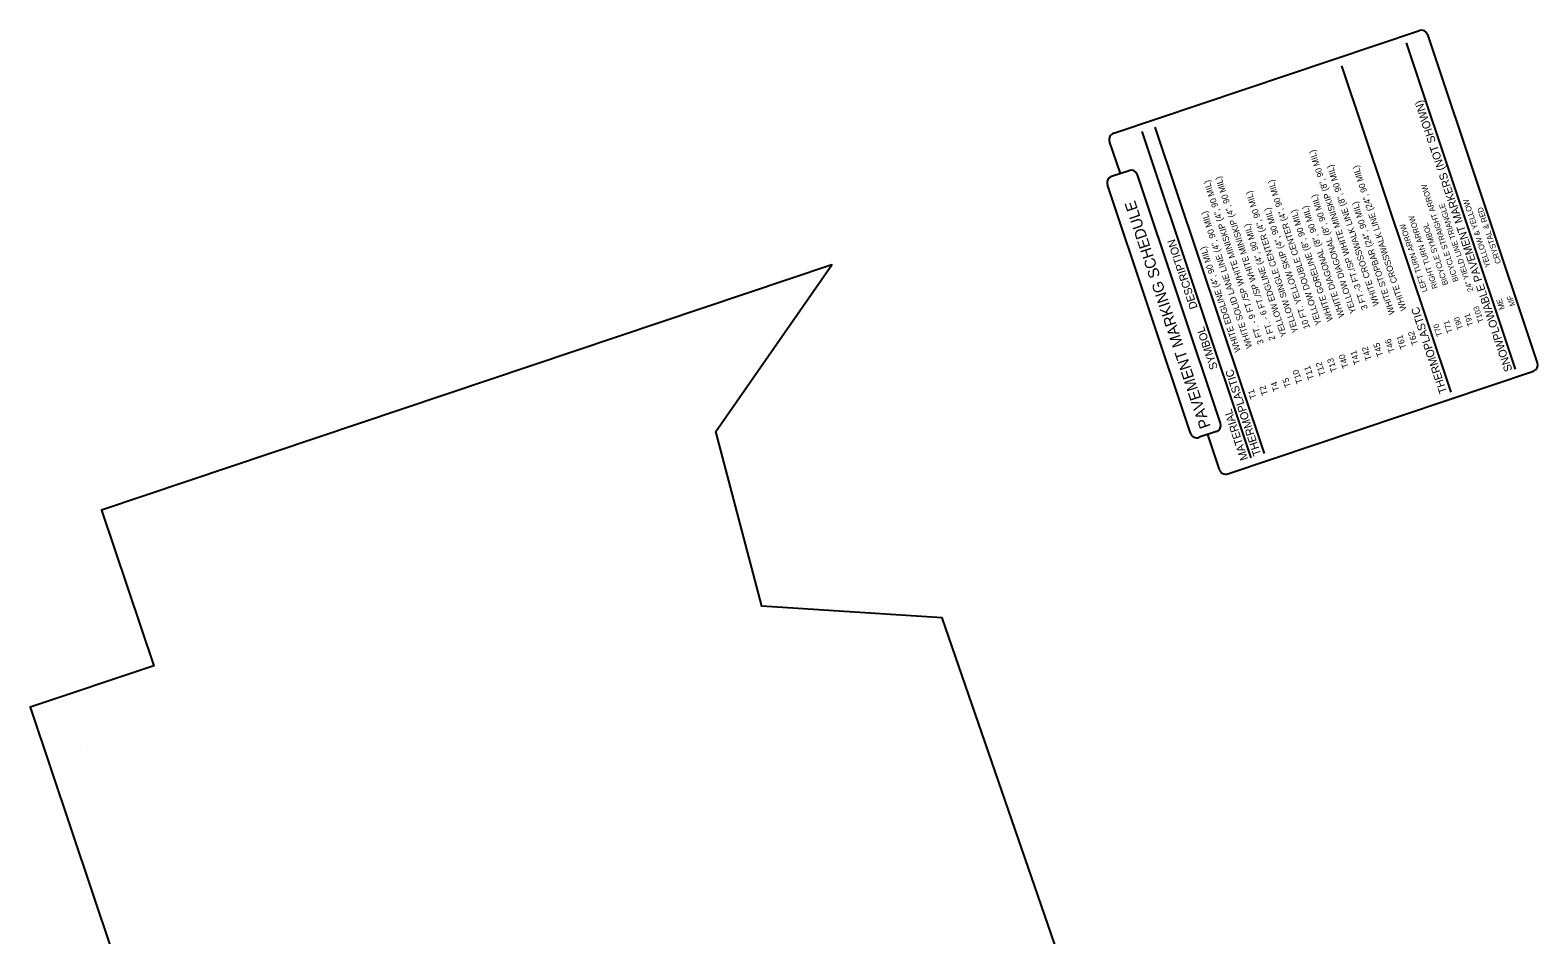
# Model space of a CAD drawing. Extents: x 1615560 to 1617263, y 903232 to 905275.
import ezdxf

# ---------------------------------------------------------------- set-up
doc = ezdxf.new("R2010")
doc.units = 0
for name, color, linetype in [('DEV BORDER CELL', 7, 'Continuous'), ('Gray Area Fill Shapes', 7, 'Continuous'), ('Sheet Layout Plan Border', 7, 'Continuous'), ('Sheet North Arrow Point CELL', 7, 'Continuous'), ('Sheet Title CELL', 7, 'Continuous')]:
    doc.layers.add(name, color=color, linetype=linetype)

msp = doc.modelspace()

# ---------------------------------------------------------------- linework, layer by layer
at = {"layer": 'DEV BORDER CELL'}
for p, q in [((1617238.1, 904891.9), (1617114.8, 905260.3)), ((1617165.3, 904866), (1617041.9, 905234.3)), ((1616939.6, 904791.9), (1616816.3, 905160.3)), ((1616954.4, 904796.8), (1616831.1, 905165.3))]:
    msp.add_line(p, q, dxfattribs=at)
at = {"layer": 'Sheet Layout Plan Border'}
msp.add_lwpolyline([(1616672.6, 903656.2), (1616919.8, 903656.8), (1616590.6, 904611.2), (1616386.8, 904624.4), (1616334.8, 904821.6), (1616466, 905009.6), (1615641.1, 904732.9), (1615700, 904557.2), (1615560.3, 904510.3), (1615954.2, 903336.2)], close=True, dxfattribs=at)
at = {"layer": 'Sheet North Arrow Point CELL'}
msp.add_line((1615617.6, 904466.6), (1615617.6, 904466.6), dxfattribs=at)
at = {"layer": 'Sheet Title CELL'}
for p, q in [((1616784.3, 905158.3), (1617129.6, 905274.3)), ((1617263, 904899.2), (1617138.9, 905269.6)), ((1616791.8, 905112.7), (1616779.6, 905149)), ((1616801.8, 905116), (1616781.8, 905109.4)), ((1616905, 904830.9), (1616811.1, 905111.4)), ((1616871.1, 904819.6), (1616777.2, 905100)), ((1616913.1, 904773.9), (1617258.3, 904889.9)), ((1616900.4, 904821.6), (1616880.8, 904815.1)), ((1616903.7, 904778.6), (1616890.4, 904818.3))]:
    msp.add_line(p, q, dxfattribs=at)
for centre, start, end in [((1617131.9, 905267.3), 18.5124, 108.5124), ((1616786.6, 905151.4), 108.5124, 198.5124), ((1616784.1, 905102.4), 108.4822, 198.5425), ((1616804.1, 905109.1), 18.5425, 108.5425), ((1617256, 904896.8), 288.5124, 18.5124), ((1616878.1, 904821.9), 198.5425, 291.6591), ((1616898, 904828.6), 288.5425, 18.5425), ((1616910.7, 904780.9), 198.5124, 288.5124)]:
    msp.add_arc(centre, 7.36, start, end, dxfattribs=at)

# ---------------------------------------------------------------- texts
at = {"layer": 'DEV BORDER CELL'}
for s, height, rotation, p in [('SNOWPLOWABLE PAVEMENT MARKERS (NOT SHOWN)', 9, 108.503, (1617234.7, 904890.8)), ('3 FT.-3 FT./SP WHITE MINISKIP (8", 90 MIL)', 7, 108.4456, (1617071.3, 904960.4)), ('2 FT. - 6 FT./SP WHITE MINISKIP (4", 90 MIL)', 7, 108.4456, (1616967, 904925.6)), ('WHITE CROSSWALK LINE (8", 90 MIL)', 7, 108.4456, (1617084.3, 904964.8)), ('     WHITE CROSSWALK LINE (24", 90 MIL)', 7, 108.4456, (1617119.2, 904946.9)), ('3 FT. - 9 FT./SP WHITE MINISKIP (4", 90 MIL)', 7, 108.4456, (1616953.9, 904921.3)), ('YELLOW SINGLE CENTER (4", 90 MIL)', 7, 108.4456, (1616993, 904934.3)), ('YELLOW DOUBLE CENTER (4", 90 MIL)', 7, 108.4456, (1617019.1, 904943)), (' BICYCLE STRAIGHT ARROW', 6.3, 108.4722, (1617174.7, 904989.5)), ('10 FT. YELLOW SKIP (4", 90 MIL)', 7, 108.4456, (1617006.1, 904938.7)), ('WHITE DIAGONAL (8", 90 MIL)', 7, 108.4456, (1617045.2, 904951.7)), ('YELLOW DIAGONAL (8", 90 MIL)', 7, 108.4456, (1617058.2, 904956.1)), ('     WHITE STOPBAR (24", 90 MIL)', 7, 108.4456, (1617106.2, 904942.6)), ('     24" YIELD LINE TRIANGLE', 6.3, 108.4722, (1617194.3, 904969.5)), ('YELLOW & YELLOW', 6.3, 108.503, (1617210.2, 905008.2)), ('CRYSTAL & RED', 6.3, 108.503, (1617221.9, 905012.1)), ('WHITE SOLID LANE LINE (4", 90 MIL)', 7, 108.4456, (1616940.9, 904916.9)), ('YELLOW EDGLINE (4", 90 MIL)', 7, 108.4456, (1616980, 904930)), ('WHITE GORELINE (8", 90 MIL)', 7, 108.4456, (1617032.2, 904947.4)), (' LEFT TURN ARROW', 6.3, 108.4722, (1617139.6, 904977.8)), (' RIGHT TURN ARROW', 6.3, 108.4722, (1617151.3, 904981.7)), (' BICYCLE SYMBOL', 6.3, 108.4722, (1617163, 904985.6)), ('DESCRIPTION', 9, 108.4722, (1616879.2, 904961.5)), ('WHITE EDGLINE (4", 90 MIL)', 7, 108.4456, (1616927.8, 904912.6)), ('ME', 6.3, 108.503, (1617226.2, 904960.4)), ('MF', 6.3, 108.503, (1617237.9, 904964.3)), ('THERMOPLASTIC', 9, 108.4722, (1617161, 904866.1)), ('T91', 6.3, 108.4722, (1617190.6, 904941.7)), ('T103', 6.3, 108.4722, (1617202.3, 904945.6)), ('SYMBOL', 9, 108.4722, (1616902, 904893.2)), ('T70', 6.3, 108.4722, (1617155.5, 904930)), ('T71', 6.3, 108.4722, (1617167.2, 904933.9)), ('T90', 6.3, 108.4722, (1617178.9, 904937.8)), ('T45', 7, 108.4456, (1617089, 904907.3)), ('T46', 7, 108.4456, (1617102, 904911.7)), ('T61', 7, 108.4456, (1617115.1, 904916)), ('T62', 7, 108.4456, (1617128.1, 904920.4)), ('T13', 7, 108.4456, (1617036.8, 904889.9)), ('T40', 7, 108.4456, (1617049.9, 904894.3)), ('T41', 7, 108.4456, (1617062.9, 904898.6)), ('T42', 7, 108.4456, (1617075.9, 904903)), ('THERMOPLASTIC', 9, 108.4722, (1616951, 904795.7)), ('T10', 7, 108.4456, (1616997.7, 904876.9)), ('T11', 7, 108.4456, (1617010.8, 904881.2)), ('T12', 7, 108.4456, (1617023.8, 904885.6)), ('T1', 7, 108.4456, (1616945.6, 904859.5)), ('T2', 7, 108.4456, (1616958.6, 904863.8)), ('T4', 7, 108.4456, (1616971.6, 904868.2)), ('T5', 7, 108.4456, (1616984.7, 904872.5)), ('MATERIAL', 9, 108.4722, (1616936.2, 904790.7))]:
    msp.add_text(s, height=height, rotation=rotation, dxfattribs=at).set_placement(p)
at = {"layer": 'Gray Area Fill Shapes'}
msp.add_text('PAVEMENT MARKING SCHEDULE', height=12.479, rotation=108.5124, dxfattribs=at).set_placement((1616893.8, 904827.4))

doc.saveas('drawing.dxf')
